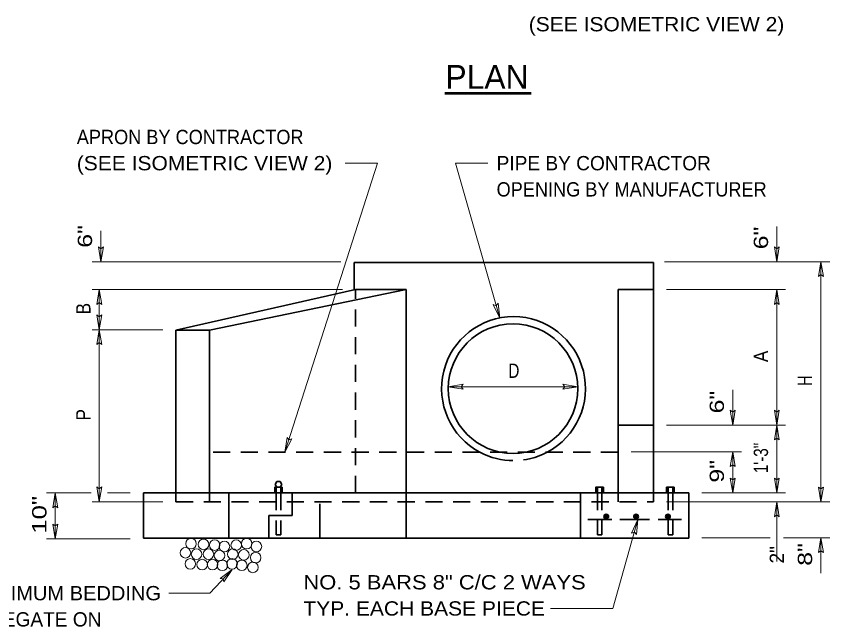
# Model space of a CAD drawing. Extents: x 178962.5 to 178977.5, y 178951.2 to 178972.9.
# Drawn here: x 178969.81 to 178977.5, y 178960.79 to 178966.56 of the extents above; entities that cross this region are included whole.
import ezdxf
from ezdxf.enums import TextEntityAlignment as Align

# ---------------------------------------------------------------- set-up
doc = ezdxf.new("R2010")
doc.units = 0
doc.header["$LTSCALE"] = 0.054
doc.linetypes.add('LONG_DASHED', pattern=[7.5, 6, -1.5])
doc.linetypes.add('MEDIUM_DASHED', pattern=[4.5, 3, -1.5])
for name, color, linetype, lineweight in [('1', 7, 'Continuous', 35), ('10', 7, 'Continuous', 13), ('12', 7, 'Continuous', 53), ('6', 7, 'Continuous', 13)]:
    doc.layers.add(name, color=color, linetype=linetype, lineweight=lineweight)

msp = doc.modelspace()

# ---------------------------------------------------------------- linework, layer by layer
at = {"layer": '1'}
for p, q in [((178973.0045, 178963.97633), (178973.0045, 178964.23233)), ((178973.0045, 178964.23233), (178975.83367, 178964.23233)), ((178975.83367, 178961.96908), (178975.83367, 178964.23233)), ((178971.3195, 178963.59042), (178973.01817, 178963.97442)), ((178971.63658, 178963.59042), (178973.49708, 178963.97442)), ((178973.01817, 178963.97442), (178973.49708, 178963.97442)), ((178973.49708, 178961.62383), (178973.49708, 178963.97442)), ((178975.49983, 178961.96908), (178975.49983, 178963.97442)), ((178975.49983, 178963.97442), (178975.83367, 178963.97442)), ((178971.3195, 178963.59042), (178971.63658, 178963.59042)), ((178971.3195, 178961.96908), (178971.3195, 178963.59042)), ((178971.63658, 178961.96908), (178971.63658, 178963.59042)), ((178975.49983, 178962.69442), (178975.83367, 178962.69442)), ((178972.26825, 178962.10592), (178972.26825, 178962.05442)), ((178972.31208, 178962.10633), (178972.31208, 178962.05442)), ((178972.32508, 178962.10717), (178972.32508, 178962.05442)), ((178975.30367, 178962.10592), (178975.30367, 178962.05442)), ((178975.3475, 178962.10633), (178975.3475, 178962.05442)), ((178975.3605, 178962.10717), (178975.3605, 178962.05442)), ((178975.97317, 178962.10592), (178975.97317, 178962.05442)), ((178976.017, 178962.10633), (178976.017, 178962.05442)), ((178976.03, 178962.10717), (178976.03, 178962.05442)), ((178971.0115, 178961.62775), (178971.0115, 178962.05442)), ((178971.0115, 178962.05442), (178976.1675, 178962.05442)), ((178971.82075, 178961.62775), (178971.82075, 178962.05442)), ((178972.41667, 178961.84183), (178972.41667, 178962.05442)), ((178975.14383, 178961.62775), (178975.14383, 178962.05442)), ((178976.1675, 178961.62775), (178976.1675, 178962.05442)), ((178972.19742, 178961.84183), (178972.41667, 178961.84183)), ((178972.19742, 178961.84183), (178972.19742, 178961.62775)), ((178975.21433, 178961.80292), (178975.44108, 178961.80292)), ((178975.39217, 178961.85175), (178975.36575, 178961.82808)), ((178975.38433, 178961.852), (178975.36633, 178961.836)), ((178975.39792, 178961.8495), (178975.36725, 178961.82208)), ((178975.4025, 178961.84625), (178975.37, 178961.81725)), ((178975.40592, 178961.842), (178975.37383, 178961.81333)), ((178975.40833, 178961.83683), (178975.37875, 178961.81042)), ((178975.40933, 178961.83042), (178975.385, 178961.80867)), ((178975.40742, 178961.82133), (178975.39417, 178961.80958)), ((178975.51583, 178961.80292), (178975.79558, 178961.80292)), ((178975.67442, 178961.85167), (178975.64792, 178961.828)), ((178975.6665, 178961.85192), (178975.6485, 178961.83592)), ((178975.68017, 178961.8495), (178975.64942, 178961.82208)), ((178975.68458, 178961.84625), (178975.65217, 178961.81725)), ((178975.68817, 178961.842), (178975.656, 178961.81325)), ((178975.6905, 178961.83692), (178975.66083, 178961.81033)), ((178975.6915, 178961.83033), (178975.66717, 178961.80867)), ((178975.68958, 178961.82125), (178975.67642, 178961.80958)), ((178976.0995, 178961.80292), (178975.88008, 178961.80292)), ((178975.97592, 178961.85175), (178975.9495, 178961.82808)), ((178975.96808, 178961.852), (178975.95008, 178961.836)), ((178975.98167, 178961.8495), (178975.951, 178961.82208)), ((178975.98617, 178961.84625), (178975.95375, 178961.81725)), ((178975.98967, 178961.842), (178975.9575, 178961.81333)), ((178975.99208, 178961.83683), (178975.9625, 178961.81042)), ((178975.993, 178961.83042), (178975.96867, 178961.80867)), ((178975.99108, 178961.82133), (178975.97792, 178961.80958)), ((178971.0115, 178961.62775), (178976.1675, 178961.62775))]:
    msp.add_line(p, q, dxfattribs=at)
at = {"layer": '1', "linetype": 'MEDIUM_DASHED'}
for p, q in [((178973.01817, 178962.05442), (178973.01817, 178963.97442)), ((178975.49983, 178962.43842), (178971.63658, 178962.43842)), ((178972.31208, 178962.05442), (178972.31208, 178961.65942)), ((178975.3475, 178962.05442), (178975.3475, 178961.65942)), ((178976.017, 178962.05442), (178976.017, 178961.65942)), ((178971.3195, 178961.96908), (178975.83367, 178961.96908))]:
    msp.add_line(p, q, dxfattribs=at)
at = {"layer": '1', "linetype": 'LONG_DASHED'}
msp.add_line((178972.67842, 178961.62775), (178972.67842, 178962.05442), dxfattribs=at)
at = {"layer": '1'}
for points in [[(178972.32508, 178962.10717), (178972.25333, 178962.10717), (178972.25333, 178962.05442)], [(178975.3605, 178962.10717), (178975.28875, 178962.10717), (178975.28875, 178962.05442)], [(178976.03, 178962.10717), (178975.95825, 178962.10717), (178975.95825, 178962.05442)]]:
    msp.add_lwpolyline(points, dxfattribs=at)
at = {"layer": '1', "linetype": 'MEDIUM_DASHED'}
msp.add_lwpolyline([(178972.25792, 178962.13425), (178972.27358, 178962.16125), (178972.30492, 178962.16125), (178972.32042, 178962.13425), (178972.30492, 178962.10717), (178972.27358, 178962.10717)], close=True, dxfattribs=at)
for points in [[(178972.26825, 178962.05442), (178972.26825, 178961.65942), (178972.31208, 178961.65942)], [(178975.30367, 178962.05442), (178975.30367, 178961.65942), (178975.3475, 178961.65942)], [(178975.97317, 178962.05442), (178975.97317, 178961.65942), (178976.017, 178961.65942)]]:
    msp.add_lwpolyline(points, dxfattribs=at)
at = {"layer": '1'}
for centre, radius in [((178974.50616, 178963.03954), 0.61222), ((178975.38747, 178961.83039), 0.02184), ((178975.66966, 178961.83035), 0.02184), ((178975.97122, 178961.83039), 0.02184)]:
    msp.add_circle(centre, radius, dxfattribs=at)
msp.add_arc((178974.51111, 178963.03984), 0.68024, 297.85603, 242.14396, dxfattribs=at)
at = {"layer": '1', "linetype": 'LONG_DASHED'}
msp.add_arc((178974.51111, 178963.03984), 0.68024, 242.14396, 297.85603, dxfattribs=at)
at = {"layer": '10'}
for p, q in [((178973.962, 178965.16908), (178974.26767, 178965.16908)), ((178973.962, 178965.16908), (178974.38058, 178963.70483)), ((178977.00083, 178964.57175), (178977.00083, 178964.23842)), ((178970.60933, 178964.53008), (178970.60933, 178964.23842)), ((178970.586, 178964.37842), (178970.60933, 178964.23842)), ((178970.586, 178964.37842), (178970.60933, 178964.36092)), ((178970.63267, 178964.37842), (178970.60933, 178964.23842)), ((178970.63267, 178964.37842), (178970.60933, 178964.36092)), ((178976.9775, 178964.37842), (178977.00083, 178964.23842)), ((178976.9775, 178964.37842), (178977.00083, 178964.36092)), ((178977.02417, 178964.37842), (178977.00083, 178964.23842)), ((178977.02417, 178964.37842), (178977.00083, 178964.36092)), ((178972.8795, 178964.23842), (178970.526, 178964.23842)), ((178975.9375, 178964.23842), (178977.50083, 178964.23842)), ((178977.39417, 178964.09842), (178977.4175, 178964.23842)), ((178977.44083, 178964.09842), (178977.4175, 178964.23842)), ((178977.4175, 178964.23842), (178977.4175, 178961.96908)), ((178977.39417, 178964.09842), (178977.4175, 178964.11592)), ((178977.44083, 178964.09842), (178977.4175, 178964.11592)), ((178970.526, 178963.97442), (178972.89317, 178963.97442)), ((178970.5715, 178963.83442), (178970.59483, 178963.97442)), ((178970.59483, 178963.97442), (178970.59483, 178963.59633)), ((178970.61817, 178963.83442), (178970.59483, 178963.97442)), ((178977.08417, 178963.97442), (178975.95867, 178963.97442)), ((178976.9775, 178963.83442), (178977.00083, 178963.97442)), ((178977.02417, 178963.83442), (178977.00083, 178963.97442)), ((178977.00083, 178963.97442), (178977.00083, 178962.69442)), ((178970.5715, 178963.83442), (178970.59483, 178963.85192)), ((178970.61817, 178963.83442), (178970.59483, 178963.85192)), ((178974.31967, 178963.833), (178974.38058, 178963.70483)), ((178974.31967, 178963.833), (178974.34692, 178963.82258)), ((178974.3645, 178963.84583), (178974.34692, 178963.82258)), ((178974.3645, 178963.84583), (178974.38058, 178963.70483)), ((178976.9775, 178963.83442), (178977.00083, 178963.85192)), ((178977.02417, 178963.83442), (178977.00083, 178963.85192)), ((178970.5715, 178963.73633), (178970.59483, 178963.59633)), ((178970.5715, 178963.73633), (178970.59483, 178963.71883)), ((178970.61817, 178963.73633), (178970.59483, 178963.59633)), ((178970.61817, 178963.73633), (178970.59483, 178963.71883)), ((178971.1945, 178963.59633), (178970.526, 178963.59633)), ((178970.5715, 178963.45633), (178970.59483, 178963.59633)), ((178970.59483, 178961.96908), (178970.59483, 178963.59633)), ((178970.61817, 178963.45633), (178970.59483, 178963.59633)), ((178970.5715, 178963.45633), (178970.59483, 178963.47383)), ((178970.61817, 178963.45633), (178970.59483, 178963.47383)), ((178974.03417, 178963.081), (178973.89417, 178963.05767)), ((178974.03417, 178963.03433), (178973.89417, 178963.05767)), ((178973.89417, 178963.05767), (178975.11808, 178963.05767)), ((178974.03417, 178963.081), (178974.01667, 178963.05767)), ((178974.03417, 178963.03433), (178974.01667, 178963.05767)), ((178974.97808, 178963.081), (178975.11808, 178963.05767)), ((178974.97808, 178963.081), (178974.99558, 178963.05767)), ((178974.97808, 178963.03433), (178975.11808, 178963.05767)), ((178974.97808, 178963.03433), (178974.99558, 178963.05767)), ((178976.58417, 178963.02775), (178976.58417, 178962.69442)), ((178976.56083, 178962.83442), (178976.58417, 178962.69442)), ((178976.56083, 178962.83442), (178976.58417, 178962.81692)), ((178976.6075, 178962.83442), (178976.58417, 178962.69442)), ((178976.6075, 178962.83442), (178976.58417, 178962.81692)), ((178976.9775, 178962.83442), (178977.00083, 178962.69442)), ((178976.9775, 178962.83442), (178977.00083, 178962.81692)), ((178977.02417, 178962.83442), (178977.00083, 178962.69442)), ((178977.02417, 178962.83442), (178977.00083, 178962.81692)), ((178977.08417, 178962.69442), (178975.95867, 178962.69442)), ((178976.9775, 178962.55442), (178977.00083, 178962.69442)), ((178977.00083, 178962.05442), (178977.00083, 178962.69442)), ((178977.02417, 178962.55442), (178977.00083, 178962.69442)), ((178972.36967, 178962.57883), (178972.34917, 178962.43842)), ((178972.41408, 178962.56467), (178972.34917, 178962.43842)), ((178972.36967, 178962.57883), (178972.3865, 178962.55508)), ((178972.41408, 178962.56467), (178972.3865, 178962.55508)), ((178976.9775, 178962.55442), (178977.00083, 178962.57192)), ((178977.02417, 178962.55442), (178977.00083, 178962.57192)), ((178975.62483, 178962.44317), (178976.6675, 178962.44317)), ((178976.56083, 178962.30317), (178976.58417, 178962.44317)), ((178976.58417, 178962.05442), (178976.58417, 178962.44317)), ((178976.6075, 178962.30317), (178976.58417, 178962.44317)), ((178976.56083, 178962.30317), (178976.58417, 178962.32067)), ((178976.6075, 178962.30317), (178976.58417, 178962.32067)), ((178976.56083, 178962.19442), (178976.58417, 178962.05442)), ((178976.56083, 178962.19442), (178976.58417, 178962.17692)), ((178976.6075, 178962.19442), (178976.58417, 178962.05442)), ((178976.6075, 178962.19442), (178976.58417, 178962.17692)), ((178976.9775, 178962.19442), (178977.00083, 178962.05442)), ((178976.9775, 178962.19442), (178977.00083, 178962.17692)), ((178977.02417, 178962.19442), (178977.00083, 178962.05442)), ((178977.02417, 178962.19442), (178977.00083, 178962.17692)), ((178970.5715, 178962.11142), (178970.59483, 178961.97142)), ((178970.5715, 178962.11142), (178970.59483, 178962.09392)), ((178970.61817, 178962.11142), (178970.59483, 178961.97142)), ((178970.61817, 178962.11142), (178970.59483, 178962.09392)), ((178977.39417, 178962.10908), (178977.4175, 178961.96908)), ((178977.39417, 178962.10908), (178977.4175, 178962.09158)), ((178977.44083, 178962.10908), (178977.4175, 178961.96908)), ((178977.44083, 178962.10908), (178977.4175, 178962.09158)), ((178970.09483, 178962.05442), (178970.5185, 178962.05442)), ((178970.15483, 178961.91383), (178970.17817, 178962.05383)), ((178970.17817, 178962.05442), (178970.17817, 178961.62058)), ((178970.2015, 178961.91383), (178970.17817, 178962.05383)), ((178970.8865, 178962.05442), (178970.67117, 178962.05442)), ((178977.08417, 178962.05442), (178976.2925, 178962.05442)), ((178971.1945, 178961.96908), (178970.526, 178961.96908)), ((178977.50083, 178961.96908), (178975.95867, 178961.96908)), ((178976.9775, 178961.82908), (178977.00083, 178961.96908)), ((178977.00083, 178961.40575), (178977.00083, 178961.96908)), ((178977.02417, 178961.82908), (178977.00083, 178961.96908)), ((178970.15483, 178961.91383), (178970.17817, 178961.93133)), ((178970.2015, 178961.91383), (178970.17817, 178961.93133)), ((178975.68775, 178961.80292), (178975.45117, 178960.963)), ((178975.62742, 178961.67458), (178975.68775, 178961.80292)), ((178975.67225, 178961.66183), (178975.68775, 178961.80292)), ((178976.9775, 178961.82908), (178977.00083, 178961.84658)), ((178977.02417, 178961.82908), (178977.00083, 178961.84658)), ((178970.15483, 178961.76058), (178970.17817, 178961.62058)), ((178970.15483, 178961.76058), (178970.17817, 178961.74308)), ((178970.2015, 178961.76058), (178970.17817, 178961.62058)), ((178970.2015, 178961.76058), (178970.17817, 178961.74308)), ((178975.62742, 178961.67458), (178975.65458, 178961.685)), ((178975.67225, 178961.66183), (178975.65458, 178961.685)), ((178976.2925, 178961.63067), (178976.93833, 178961.63067)), ((178977.50083, 178961.63067), (178977.06333, 178961.63067)), ((178977.39417, 178961.49067), (178977.4175, 178961.63067)), ((178977.4175, 178961.29733), (178977.4175, 178961.63067)), ((178977.44083, 178961.49067), (178977.4175, 178961.63067)), ((178970.8865, 178961.62058), (178970.09483, 178961.62058)), ((178977.39417, 178961.49067), (178977.4175, 178961.50817)), ((178977.44083, 178961.49067), (178977.4175, 178961.50817)), ((178971.73683, 178961.24508), (178971.84967, 178961.33117)), ((178971.77083, 178961.21317), (178971.84967, 178961.33117)), ((178971.73683, 178961.24508), (178971.76583, 178961.24192)), ((178971.77083, 178961.21317), (178971.76583, 178961.24192)), ((178975.45117, 178960.963), (178974.86008, 178960.963))]:
    msp.add_line(p, q, dxfattribs=at)
for points in [[(178972.91817, 178965.16908), (178973.22383, 178965.16908), (178972.34917, 178962.43842)], [(178971.25142, 178961.10742), (178971.6395, 178961.10742), (178971.84967, 178961.33117)]]:
    msp.add_lwpolyline(points, dxfattribs=at)
at = {"layer": '12'}
msp.add_line((178973.86108, 178965.8295), (178974.67933, 178965.8295), dxfattribs=at)
at = {"layer": '6'}
for centre in [(178971.46175, 178961.57467), (178971.58008, 178961.56808), (178971.68533, 178961.5615), (178971.77733, 178961.54833), (178971.88917, 178961.5615), (178971.98775, 178961.57467), (178972.07983, 178961.54833), (178971.40917, 178961.48908), (178971.51433, 178961.476), (178971.62617, 178961.476), (178971.73133, 178961.46283), (178971.85625, 178961.476), (178971.96142, 178961.46942), (178972.07325, 178961.44308), (178971.45517, 178961.38383), (178971.567, 178961.37725), (178971.66558, 178961.37725), (178971.75767, 178961.37067), (178971.84967, 178961.38383), (178971.94175, 178961.37067), (178972.04692, 178961.35092)]:
    msp.add_circle(centre, 0.05, dxfattribs=at)

# ---------------------------------------------------------------- texts
at = {"layer": '12'}
for s, width, p in [('(SEE ISOMETRIC VIEW 2)', 1.1, (178974.65508, 178966.41433)), ('APRON BY CONTRACTOR', 0.95, (178970.38167, 178965.34908)), ('(SEE ISOMETRIC VIEW 2)', 1.1, (178970.38167, 178965.10158)), ('OPENING BY MANUFACTURER', 0.95, (178974.351, 178964.85408)), ('NO. 5 BARS 8" C/C 2 WAYS', 1.15, (178972.52408, 178961.143)), ('PROVIDE 6" MINIMUM BEDDING', 1.05, (178968.27775, 178961.03992)), ('TYP. EACH BASE PIECE', 1.1, (178972.52408, 178960.8955))]:
    msp.add_text(s, height=0.135, dxfattribs=dict(at, width=width)).set_placement(p)
msp.add_text('PLAN', height=0.225, dxfattribs=at).set_placement((178974.26004, 178965.87133), align=Align.CENTER)
for s, p in [('PIPE BY CONTRACTOR', (178974.351, 178965.10158)), ('OF NO.57 AGGREGATE ON', (178968.27775, 178960.79242))]:
    msp.add_text(s, height=0.135, dxfattribs=at).set_placement(p)
for s, width, p in [('6"', 1.3, (178970.52592, 178964.47708)), ('6"', 1.3, (178976.91742, 178964.4625)), ('B', 0.9, (178970.51142, 178963.79483)), ('A', 0.9, (178976.91742, 178963.34387)), ('H', 0.75, (178977.33408, 178963.11325)), ('6"', 1.3, (178976.50075, 178962.91225)), ('P', 0.9, (178970.51142, 178962.79217)), ('1\'-3"', 0.8, (178976.91742, 178962.38392)), ('9"', 1.3, (178976.50075, 178962.25833)), ('10"', 1.35, (178970.09475, 178961.847)), ('8"', 1.3, (178977.33408, 178961.473))]:
    msp.add_text(s, height=0.135, rotation=90, dxfattribs=dict(at, width=width)).set_placement(p, align=Align.CENTER)
at = {"layer": '12', "width": 0.8}
msp.add_text('D', height=0.135, dxfattribs=at).set_placement((178974.51408, 178963.141), align=Align.CENTER)
at = {"layer": '12'}
msp.add_text('2"', height=0.135, rotation=90, dxfattribs=at).set_placement((178977.06833, 178961.55188), align=Align.RIGHT)

doc.saveas('drawing.dxf')
